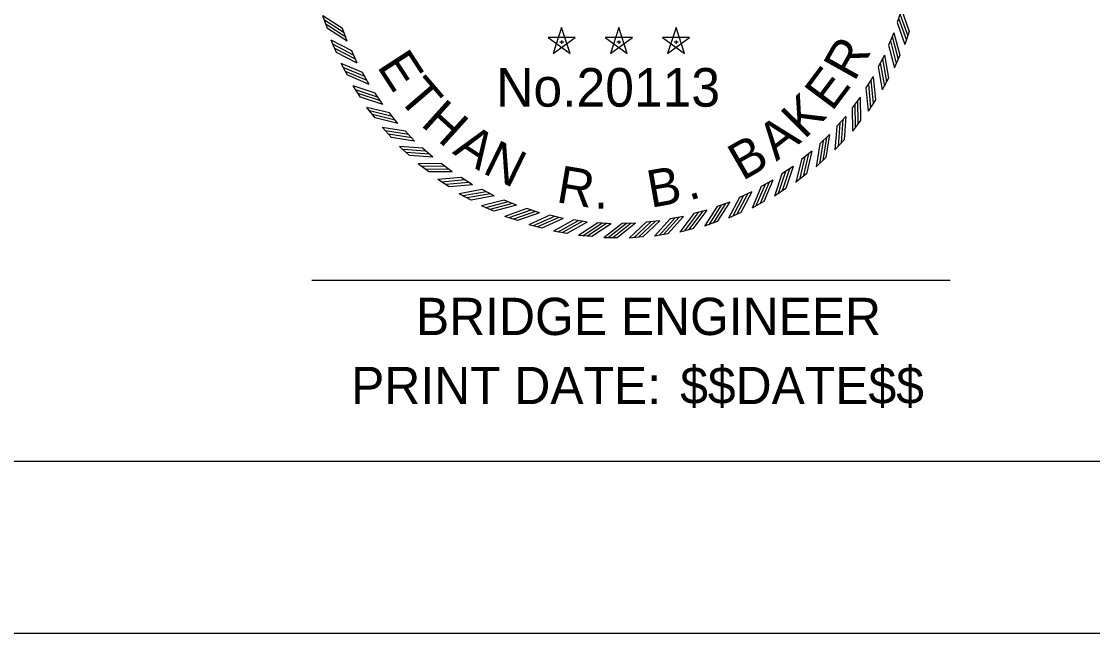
# Model space of a CAD drawing. Extents: x 18 to 14744716, y -5 to 1829144.
# Drawn here: x 41.086 to 44.681, y -5.372 to -3.319 of the extents above; entities that cross this region are included whole.
import ezdxf

# ---------------------------------------------------------------- set-up
doc = ezdxf.new("R2010")
doc.units = 0
for name, color, linetype in [('B_border', 7, 'Continuous'), ('B_Print_Date_Text', 7, 'Continuous'), ('B_StampERBB', 7, 'Continuous'), ('B_Text', 7, 'Continuous'), ('R_Border', 7, 'Continuous'), ('R_No Plot', 7, 'Continuous')]:
    doc.layers.add(name, color=color, linetype=linetype)

msp = doc.modelspace()

# ---------------------------------------------------------------- linework, layer by layer
at = {"layer": 'B_border'}
msp.add_line((42.0609, -4.1872), (44.2029, -4.1872), dxfattribs=at)
msp.add_line((42.0609, -4.1872), (44.2029, -4.1872), dxfattribs=at)
at = {"layer": 'B_StampERBB'}
for p, q in [((42.1134, -3.3429), (42.0983, -3.3002)), ((44.039, -3.2791), (44.0247, -3.3221)), ((42.1794, -3.385), (42.1642, -3.3423)), ((42.899, -3.3392), (42.8707, -3.4261)), ((42.9272, -3.426), (42.8991, -3.3391)), ((43.0909, -3.3392), (43.0626, -3.4261)), ((43.1191, -3.426), (43.091, -3.3391)), ((43.2828, -3.3392), (43.2545, -3.4261)), ((43.311, -3.426), (43.2828, -3.3391)), ((42.9446, -3.3724), (42.8533, -3.3723)), ((42.8534, -3.3724), (42.9272, -3.4261)), ((42.8708, -3.426), (42.9447, -3.3724)), ((43.1365, -3.3724), (43.0452, -3.3723)), ((43.0453, -3.3724), (43.1191, -3.4261)), ((43.0627, -3.426), (43.1366, -3.3724)), ((43.3284, -3.3724), (43.2371, -3.3723)), ((43.2372, -3.3724), (43.311, -3.4261)), ((43.2546, -3.426), (43.3285, -3.3724)), ((44.0138, -3.3564), (43.9959, -3.3981)), ((44.0652, -3.3528), (44.0509, -3.3958)), ((42.144, -3.4225), (42.1254, -3.3812)), ((42.8925, -3.387), (42.9061, -3.387)), ((42.8991, -3.3821), (42.8991, -3.3935)), ((43.0844, -3.387), (43.098, -3.387)), ((43.091, -3.3821), (43.091, -3.3935)), ((43.2763, -3.387), (43.2899, -3.387)), ((43.2829, -3.3821), (43.2829, -3.3935)), ((42.2132, -3.4591), (42.1946, -3.4177)), ((43.9822, -3.4315), (43.961, -3.4715)), ((44.0337, -3.4321), (44.016, -3.4737)), ((42.181, -3.4993), (42.1592, -3.4597)), ((42.2531, -3.53), (42.2311, -3.4903)), ((43.9446, -3.5036), (43.9202, -3.5418)), ((43.9959, -3.5086), (43.9747, -3.5485)), ((42.2243, -3.5728), (42.1992, -3.5351)), ((42.2986, -3.5974), (42.2735, -3.5597)), ((43.9012, -3.5725), (43.8737, -3.6085)), ((43.9519, -3.5816), (43.9275, -3.6197)), ((42.2735, -3.6424), (42.2454, -3.607)), ((42.3496, -3.6609), (42.3214, -3.6254)), ((43.8522, -3.6374), (43.8218, -3.6711)), ((43.902, -3.6507), (43.8745, -3.6867)), ((42.3283, -3.7078), (42.2974, -3.6748)), ((42.4057, -3.7199), (42.3746, -3.6868)), ((43.798, -3.6982), (43.7649, -3.7292)), ((43.8465, -3.7155), (43.8162, -3.7491)), ((42.3883, -3.7684), (42.3547, -3.7381)), ((42.4664, -3.7741), (42.4327, -3.7437)), ((43.739, -3.7542), (43.7035, -3.7824)), ((42.4531, -3.8238), (42.4171, -3.7964)), ((42.5314, -3.823), (42.4953, -3.7955)), ((43.6756, -3.8052), (43.6378, -3.8304)), ((43.7859, -3.7755), (43.7529, -3.8065)), ((42.6002, -3.8665), (42.562, -3.842)), ((43.7206, -3.8303), (43.6851, -3.8584)), ((42.5222, -3.8737), (42.4841, -3.8493)), ((43.6081, -3.8508), (43.5685, -3.8727)), ((43.6509, -3.8795), (43.6133, -3.9046)), ((42.5953, -3.9178), (42.5553, -3.8966)), ((42.6724, -3.9041), (42.6323, -3.8829)), ((43.5372, -3.8906), (43.4958, -3.9092)), ((42.6717, -3.9556), (42.6301, -3.9378)), ((42.7474, -3.9356), (42.7057, -3.9178)), ((42.8248, -3.9609), (42.7817, -3.9465)), ((43.3866, -3.9521), (43.3428, -3.9636)), ((43.4632, -3.9245), (43.4204, -3.9396)), ((43.5774, -3.9228), (43.5378, -3.9447)), ((42.751, -3.987), (42.7081, -3.9727)), ((42.904, -3.9796), (42.8599, -3.9689)), ((42.9844, -3.9917), (42.9396, -3.9847)), ((43.228, -3.9879), (43.1828, -3.9921)), ((43.3081, -3.9733), (43.2634, -3.9812)), ((43.5006, -3.9598), (43.4594, -3.9784)), ((42.8326, -4.0118), (42.7886, -4.0011)), ((42.916, -4.0297), (42.8713, -4.0227)), ((43.0656, -3.9972), (43.0204, -3.9939)), ((43.147, -3.9959), (43.1017, -3.9963)), ((43.3392, -4.0144), (43.2954, -4.0259)), ((43.421, -3.9904), (43.3784, -4.0055)), ((43.0005, -4.0407), (42.9554, -4.0374)), ((43.0857, -4.0446), (43.0405, -4.045)), ((43.1709, -4.0415), (43.1259, -4.0457)), ((43.2556, -4.0314), (43.2111, -4.0393))]:
    msp.add_line(p, q, dxfattribs=at)
for points in [[(42.1642, -3.3424), (42.0983, -3.3002)], [(44.0342, -3.2928), (44.0604, -3.3665)], [(44.039, -3.279), (44.0651, -3.3528)], [(42.1691, -3.3566), (42.1032, -3.3145)], [(42.1747, -3.3713), (42.1087, -3.3292)], [(44.0247, -3.322), (44.0509, -3.3958)], [(44.0296, -3.3078), (44.0558, -3.3816)], [(42.1794, -3.3851), (42.1135, -3.3429)], [(44.0079, -3.3697), (44.0279, -3.4454)], [(44.0137, -3.3564), (44.0337, -3.4321)], [(42.1946, -3.4178), (42.1254, -3.3812)], [(42.2007, -3.4316), (42.1314, -3.395)], [(42.2074, -3.4457), (42.1382, -3.4092)], [(43.996, -3.3981), (44.016, -3.4738)], [(44.002, -3.3843), (44.022, -3.46)], [(42.2133, -3.4591), (42.1441, -3.4225)], [(43.9753, -3.4442), (43.989, -3.5213)], [(43.9822, -3.4314), (43.9959, -3.5085)], [(42.2311, -3.4904), (42.1591, -3.4597)], [(42.2383, -3.5037), (42.1663, -3.4729)], [(43.9611, -3.4715), (43.9747, -3.5486)], [(43.9683, -3.4583), (43.9819, -3.5353)], [(42.2462, -3.5172), (42.1742, -3.4865)], [(42.2531, -3.53), (42.1811, -3.4993)], [(43.9367, -3.5158), (43.9439, -3.5937)], [(43.9446, -3.5036), (43.9519, -3.5815)], [(42.2735, -3.5598), (42.1992, -3.5351)], [(42.2817, -3.5724), (42.2074, -3.5477)], [(43.9202, -3.5418), (43.9275, -3.6197)], [(43.9285, -3.5292), (43.9357, -3.6071)], [(42.2907, -3.5853), (42.2164, -3.5606)], [(42.2987, -3.5975), (42.2244, -3.5728)], [(43.8922, -3.5839), (43.893, -3.6622)], [(43.9012, -3.5724), (43.902, -3.6507)], [(42.3214, -3.6254), (42.2454, -3.607)], [(42.3307, -3.6373), (42.2546, -3.6189)], [(43.8737, -3.6085), (43.8745, -3.6867)], [(43.883, -3.5966), (43.8838, -3.6749)], [(42.3407, -3.6494), (42.2647, -3.631)], [(42.3497, -3.6609), (42.2736, -3.6425)], [(43.8321, -3.66), (43.8264, -3.7381)], [(43.8423, -3.6481), (43.8367, -3.7262)], [(43.8522, -3.6374), (43.8465, -3.7155)], [(42.3746, -3.6869), (42.2973, -3.6748)], [(42.3849, -3.698), (42.3075, -3.6859)], [(42.3959, -3.7092), (42.3185, -3.6971)], [(43.798, -3.6981), (43.7859, -3.7754)], [(43.8219, -3.6711), (43.8162, -3.7491)], [(42.4057, -3.7199), (42.3284, -3.7078)], [(43.765, -3.7292), (43.7529, -3.8065)], [(43.7761, -3.719), (43.764, -3.7963)], [(43.7873, -3.708), (43.7752, -3.7853)], [(42.4328, -3.7437), (42.3547, -3.7381)], [(42.4438, -3.7539), (42.3658, -3.7483)], [(42.4557, -3.7642), (42.3777, -3.7585)], [(42.4664, -3.7741), (42.3884, -3.7684)], [(43.7154, -3.7731), (43.697, -3.8492)], [(43.7275, -3.7631), (43.7091, -3.8392)], [(43.739, -3.7542), (43.7206, -3.8302)], [(42.4954, -3.7956), (42.4171, -3.7964)], [(42.5073, -3.8048), (42.429, -3.8056)], [(43.6756, -3.8051), (43.6509, -3.8794)], [(43.7035, -3.7824), (43.6851, -3.8585)], [(42.52, -3.8141), (42.4417, -3.8149)], [(42.5314, -3.823), (42.4532, -3.8238)], [(42.562, -3.8421), (42.4841, -3.8494)], [(43.6379, -3.8304), (43.6132, -3.9046)], [(43.6505, -3.8221), (43.6259, -3.8964)], [(43.6634, -3.8131), (43.6387, -3.8874)], [(42.5746, -3.8503), (42.4967, -3.8576)], [(42.5881, -3.8585), (42.5101, -3.8658)], [(42.6003, -3.8665), (42.5223, -3.8737)], [(43.5685, -3.8727), (43.5378, -3.9447)], [(43.5818, -3.8656), (43.5511, -3.9376)], [(43.5954, -3.8576), (43.5647, -3.9296)], [(43.6082, -3.8507), (43.5775, -3.9227)], [(42.6323, -3.8829), (42.5552, -3.8966)], [(42.6456, -3.8901), (42.5685, -3.9038)], [(42.6596, -3.8972), (42.5825, -3.9108)], [(42.6724, -3.9041), (42.5954, -3.9178)], [(43.4959, -3.9092), (43.4593, -3.9784)], [(43.5097, -3.9032), (43.4731, -3.9724)], [(43.5239, -3.8964), (43.4873, -3.9656)], [(43.5372, -3.8906), (43.5007, -3.9598)], [(42.7057, -3.9178), (42.6301, -3.9378)], [(42.7195, -3.9239), (42.6439, -3.9439)], [(42.7341, -3.9298), (42.6584, -3.9498)], [(42.7475, -3.9356), (42.6718, -3.9556)], [(42.7818, -3.9466), (42.708, -3.9727)], [(42.796, -3.9515), (42.7223, -3.9776)], [(43.3867, -3.952), (43.3392, -4.0143)], [(43.4205, -3.9396), (43.3783, -4.0056)], [(43.4347, -3.9347), (43.3926, -4.0007)], [(43.4494, -3.9291), (43.4073, -3.9951)], [(43.4632, -3.9244), (43.4211, -3.9904)], [(42.8111, -3.9561), (42.7373, -3.9823)], [(42.8248, -3.9608), (42.7511, -3.987)], [(42.8599, -3.9689), (42.7886, -4.0011)], [(42.8746, -3.9726), (42.8032, -4.0048)], [(42.8899, -3.976), (42.8185, -4.0082)], [(42.904, -3.9796), (42.8327, -4.0117)], [(42.9397, -3.9847), (42.8712, -4.0227)], [(42.9546, -3.9872), (42.8861, -4.0252)], [(42.9701, -3.9893), (42.9017, -4.0273)], [(43.2135, -3.9891), (43.1565, -4.0427)], [(43.228, -3.9879), (43.171, -4.0415)], [(43.2635, -3.9812), (43.211, -4.0393)], [(43.2783, -3.9787), (43.2259, -4.0368)], [(43.2937, -3.9756), (43.2413, -4.0338)], [(43.3081, -3.9732), (43.2557, -4.0314)], [(43.3428, -3.9636), (43.2954, -4.0259)], [(43.3574, -3.9599), (43.31, -4.0222)], [(43.3726, -3.9556), (43.3251, -4.0179)], [(42.9845, -3.9917), (42.916, -4.0297)], [(43.0205, -3.9939), (42.9554, -4.0374)], [(43.0355, -3.9951), (42.9704, -4.0386)], [(43.0512, -3.996), (42.9861, -4.0394)], [(43.0657, -3.9972), (43.0006, -4.0406)], [(43.1017, -3.9964), (43.0404, -4.0451)], [(43.1168, -3.9964), (43.0555, -4.0451)], [(43.1325, -3.9959), (43.0712, -4.0446)], [(43.1471, -3.9959), (43.0858, -4.0446)], [(43.1829, -3.9921), (43.1259, -4.0457)], [(43.1979, -3.9909), (43.1409, -4.0445)]]:
    msp.add_lwpolyline(points, dxfattribs=at)
at = {"layer": 'R_Border'}
msp.add_line((51.2001, -4.7956), (19.2929, -4.7956), dxfattribs=at)
at = {"layer": 'R_No Plot'}
msp.add_lwpolyline([(17.7769, 16.6276), (51.7769, 16.6276), (51.7769, -5.3724), (17.7769, -5.3724)], close=True, dxfattribs=at)

# ---------------------------------------------------------------- texts
at = {"layer": 'B_Print_Date_Text'}
msp.add_text('PRINT DATE:', height=0.125, dxfattribs=at).set_placement((42.1926, -4.6025))
msp.add_text('$$DATE$$', height=0.125, rotation=359.9999, dxfattribs=at).set_placement((43.2969, -4.6025))
at = {"layer": 'B_StampERBB'}
for s, rotation, p in [('R', 60.8178, (43.8811, -3.5234)), ('E', 302.9873, (42.2772, -3.4696)), ('E', 53.157, (43.8061, -3.6236)), ('T', 310.6481, (42.3453, -3.5746)), ('K', 45.1314, (43.7139, -3.7168)), ('H', 317.9441, (42.4227, -3.6653)), ('A', 37.8354, (43.6195, -3.7897)), ('A', 326.6993, (42.5299, -3.76)), ('B', 29.8098, (43.5059, -3.8552)), ('N', 333.9953, (42.6293, -3.8258)), ('R', 350.4113, (42.878, -3.9244)), ('B', 10.1106, (43.198, -3.9443)), ('.', 18.1362, (43.327, -3.9209)), ('.', 358.4369, (43.0074, -3.9458))]:
    msp.add_text(s, height=0.125, rotation=rotation, dxfattribs=at).set_placement(p)
msp.add_text('No.20113', height=0.12953, dxfattribs=at).set_placement((42.6794, -3.6046))
at = {"layer": 'B_Text'}
msp.add_text('BRIDGE ENGINEER', height=0.125, dxfattribs=at).set_placement((42.4103, -4.3708))

doc.saveas('drawing.dxf')
